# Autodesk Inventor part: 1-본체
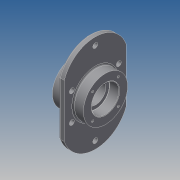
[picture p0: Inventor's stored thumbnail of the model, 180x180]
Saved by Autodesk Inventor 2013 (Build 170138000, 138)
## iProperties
Created: 2015-02
Part Number: 1-본체
Material: Generic
Document SubType Name: Modeling
Designer: kb146
Density: 1 g/cm^3
Author: kb146
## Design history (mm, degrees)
sketch "스케치2"
  geometry: L1 (-35, 31)-(-35, 50); L2 (-35, 50)-(35, 50); L3 (35, 50)-(35, 31); L4 (35, 31)-(13, 31); L5 (13, 31)-(13, 22.5); L6 (13, 22.5)-(-13, 22.5); L7 (-13, 22.5)-(-13, 31); L8 (-13, 31)-(-35, 31); L9 (-35, 0)-(35, 0); 2 further points
  constraints: 18 end point, 6 parallel, 2 vertical, 2 vertical alignment, 1 coincident, 1 midpoint, 1 perpendicular
  dimensions: "d0" = 62 diameter of L8 L9; "d2" = 45 diameter of L6 L9; "d3" = 62 diameter of L4 L9; "d4" = 100 diameter of L2 L9; "d5" = 22 distance of L7.end L1.start; "d6" = 22 distance of L3.end L4.end; "d7" = 70 distance of L1.end L2.end
revolve "회전1" sketch "스케치2" stored, may be unused: angle "d8" = 90 deg
node "작업 평면1"
sketch "스케치4"
  geometry: L1 (-70, 60)-(70, 60); L2 (70, 60)-(70, -60); L3 (70, -60)-(-70, -60); L4 (-70, -60)-(-70, 60); L5 (-70, 60)-(70, -60); L6 (70, 60)-(-70, -60); A1 r 74 centre (0, 36) between (70, 60) and (-70, 60); A2 r 74 centre (0, -36) between (-70, -60) and (70, -60); 1 further point
  constraints: 12 end point, 4 point on circle, 2 centre point, 2 midpoint, 2 parallel, 1 equal radius, 1 horizontal, 1 perpendicular
  dimensions: "d10" = 120 distance of L1.end L2.end; "d12" = 140 distance of L1.start L1.end; "d13" = 220 dimension on A2 A1
extrude "돌출1" join sketch "스케치4" distance "d14" = 12; taper "d15" = 0 deg
sketch "스케치5"
  geometry: L1 (60, 70)-(-60, 70) reference; L2 (-60, -70)-(60, -70) reference; L3 (-56.976, 53)-(56.976, 53); L4 (56.976, -53)-(-56.976, -53); L5 (-93, 0)-(93, 0); L6 (-31, 53)-(-31, -53); L7 (31, 53)-(31, -53); C1 r 10 at (-31, 53); C2 r 10 at (-93, 0); C3 r 10 at (31, 53); C4 r 10 at (-31, -53); C5 r 10 at (31, -53); C6 r 10 at (93, 0); C7 r 5.5 at (-93, 0); C8 r 5.5 at (-31, 53); C9 r 5.5 at (31, 53); C10 r 5.5 at (93, 0); C11 r 5.5 at (31, -53); C12 r 5.5 at (-31, -53); A1 r 74 centre (36, 0) between (60, -70) and (60, 70) reference; A2 r 74 centre (-36, 0) between (-60, 70) and (-60, -70) reference; A3 r 57 centre (36, 0) between (56.976, -53) and (56.976, 53); A4 r 57 centre (-36, 0) between (-56.976, 53) and (-56.976, -53)
  constraints: 14 centre point, 12 coincident, 10 end point, 6 point on circle, 5 equal radius, 4 point on line, 2 perpendicular, 3 other
  dimensions: "d16" = 17 distance between parallel lines of L3 L1; "d17" = 62 distance from line of L5.end L7; "d18" = 62 distance from line of L6 L5.start; "d19" = 20 diameter of C2; "d20" = 20 diameter of C3; "d21" = 20 diameter of C4; "d22" = 20 diameter of C5; "d23" = 20 diameter of C6; "d24" = 20 diameter of C1; "d30" = 11 diameter of C12
extrude "돌출2" join sketch "스케치5" distance "d31" = 5; taper "d32" = 0 deg
extrude "돌출3" cut sketch "스케치5" stored distance "d33" = 5; taper "d34" = 0 deg
sketch "스케치6"
  geometry: C1 r 22.5 at (0, 0) reference; C2 r 22.5 at (0, 0)
  constraints: 1 centre point, 1 coincident
  dimensions: "d35" = 45 diameter of C2
extrude "돌출4" cut sketch "스케치6" stored distance "d37" = 5; taper "d38" = 0 deg
sketch "스케치7"
  geometry: L1 (0, 0)-(-41, 0); L2 (0, 0)-(-28.991, 28.991); C1 r 50 at (0, 0) reference; C2 r 22.5 at (0, 0) reference; A1 r 41 centre (0, 0) between (-41, 0) and (-28.991, 28.991); 1 further point
  constraints: 4 end point, 2 coincident, 2 point on circle, 1 centre point, 1 horizontal
  dimensions: "d39" = 82 diameter of A1; "d40" = 45 deg angle of L2 L1
hole "구멍1" sketch "스케치7" at (-28.991, 28.991) diameter "d42" = 4.917; stored, may be unused: countersink angle "d46" = 90 deg, drill point angle "d48" = 118 deg; dims "d43" = 10, "d44" = 4, "d45" = 2, "d47" = 13
sketch "스케치8"
  geometry: C1 r 50 at (0, 0) reference; 1 further point
  constraints: 1 horizontal alignment, 1 other
  dimensions: "d52" = 65 distance of C1.centre point (65, 0)
feature "엠보싱1" sketch "스케치8" dims "d0" = 62, "d2" = 45, "d3" = 62, "d4" = 100, "d5" = 22, "d6" = 22, "d7" = 70, "d53" = 1, "d54" = 0
fillet "모깎기1" dims "d55" = 3, "d56" = 0.3
chamfer "모따기1" distance "d57" = 1; stored, may be unused: second distance "d58" = 2, angle "d59" = 45 deg
node "솔리드1"
pattern_circular "원형 패턴1" dims angle "d50" = 360 deg
mirror "대칭1"
other parameters: "d9" = -23
